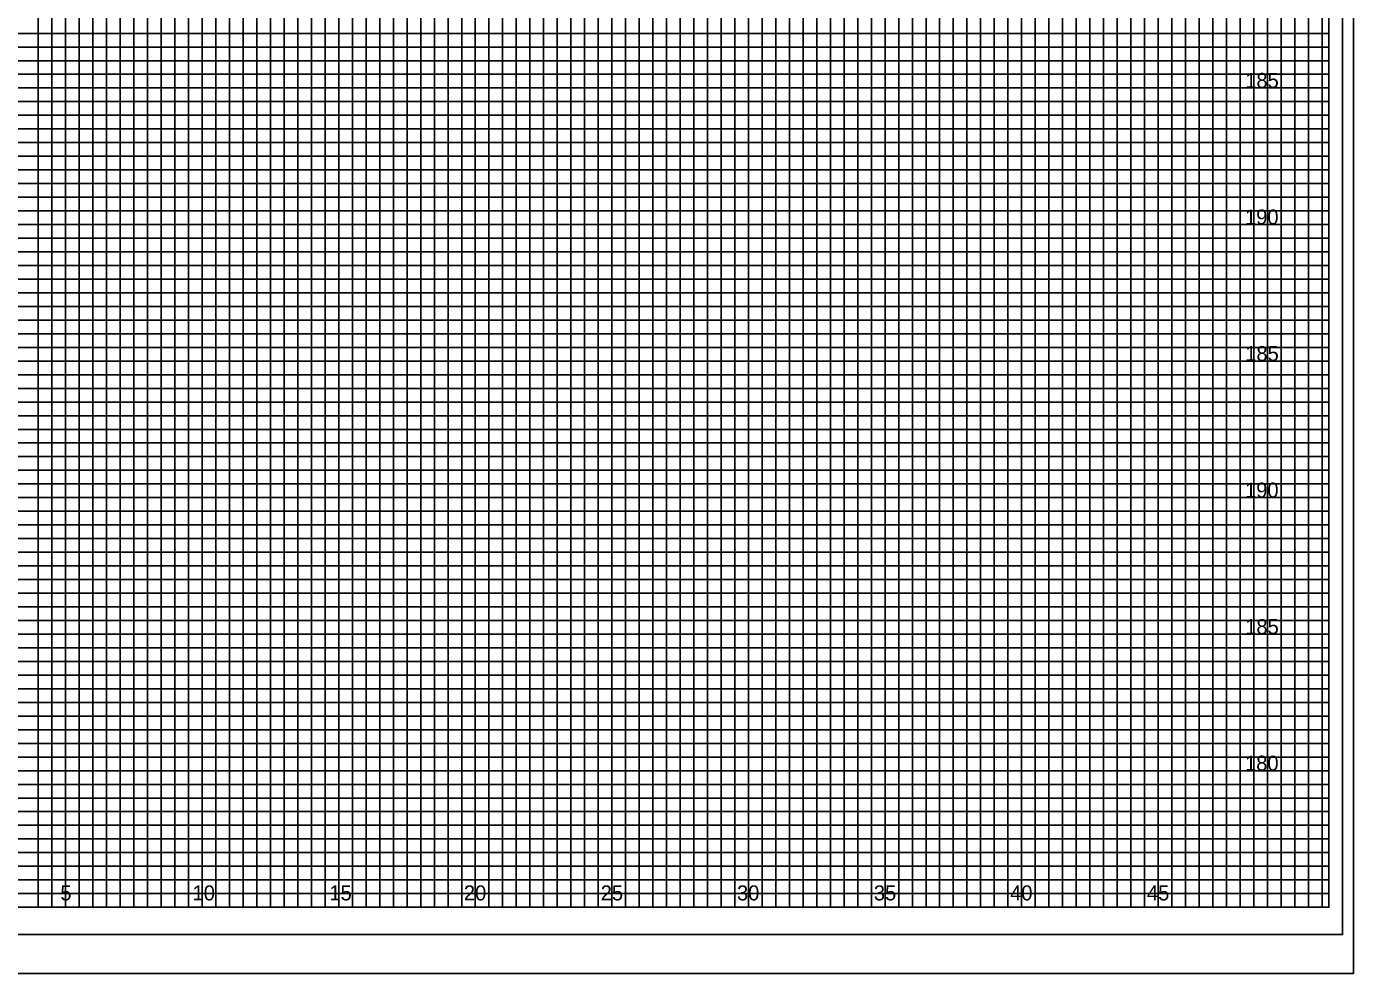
# Model space of a CAD drawing. Extents: x -4 to 103, y -2 to 138.
# Drawn here: x 54.82 to 103.4, y -2.43 to 32.25 of the extents above; entities that cross this region are included whole.
import ezdxf

# ---------------------------------------------------------------- set-up
doc = ezdxf.new("R2010")
doc.units = 0
for name, color, linetype in [('Old_Level_10', 7, 'Continuous'), ('Old_Level_16', 7, 'Continuous'), ('Old_Level_3', 7, 'Continuous'), ('Old_Level_5', 7, 'Continuous'), ('Old_Level_8', 7, 'Continuous'), ('Prop Dimension', 7, 'Continuous'), ('Prop XS SE Text', 7, 'Continuous'), ('Prop XS Subgrade Earthwork', 7, 'Continuous'), ('Prop XSC Text', 7, 'Continuous')]:
    doc.layers.add(name, color=color, linetype=linetype)

msp = doc.modelspace()

# ---------------------------------------------------------------- linework, layer by layer
at = {"layer": 'Old_Level_10'}
for p, q in [((56.25, 0), (56.25, 65)), ((58.75, 0), (58.75, 65)), ((61.25, 0), (61.25, 65)), ((63.75, 0), (63.75, 65)), ((66.25, 0), (66.25, 65)), ((68.75, 0), (68.75, 65)), ((71.25, 0), (71.25, 65)), ((73.75, 0), (73.75, 65)), ((91.25, 0), (91.25, 63.425)), ((93.75, 0), (93.75, 63.425)), ((96.25, 0), (96.25, 63.425)), ((98.75, 0), (98.75, 63.425)), ((101.25, 0), (101.25, 63.425)), ((76.25, 0), (76.25, 62)), ((78.75, 0), (78.75, 62)), ((81.25, 0), (81.25, 62)), ((83.75, 0), (83.75, 62)), ((86.25, 0), (86.25, 62)), ((88.75, 0), (88.75, 62)), ((0, 30), (102.5, 30)), ((0, 27.5), (102.5, 27.5)), ((0, 25), (102.5, 25)), ((0, 22.5), (102.5, 22.5)), ((0, 20), (102.5, 20)), ((0, 17.5), (102.5, 17.5)), ((0, 15), (102.5, 15)), ((0, 12.5), (102.5, 12.5)), ((0, 10), (102.5, 10)), ((0, 7.5), (102.5, 7.5)), ((0, 5), (102.5, 5)), ((0, 2.5), (102.5, 2.5))]:
    msp.add_line(p, q, dxfattribs=at)
at = {"layer": 'Old_Level_3'}
msp.add_line((-3.5, -2.425), (103.4, -2.425), dxfattribs=at)
at = {"layer": 'Old_Level_5'}
msp.add_lwpolyline([(103.4, 67.4), (-3.5, 67.4), (-3.5, -2.425), (103.4, -2.425)], close=True, dxfattribs=at)
at = {"layer": 'Old_Level_8'}
for points in [[(56.25, 0), (56.25, 65)], [(58.75, 65), (58.75, 0), (61.25, 0), (61.25, 65)], [(63.75, 65), (63.75, 0), (66.25, 0), (66.25, 65)], [(68.75, 65), (68.75, 0), (71.25, 0), (71.25, 65)], [(73.75, 65), (73.75, 0), (76.25, 0), (76.25, 62)], [(88.75, 62), (88.75, 0), (91.25, 0), (91.25, 63.425)], [(93.75, 63.425), (93.75, 0), (96.25, 0), (96.25, 63.425)], [(98.75, 63.425), (98.75, 0), (101.25, 0), (101.25, 63.425)], [(78.75, 62), (78.75, 0), (81.25, 0), (81.25, 62)], [(83.75, 62), (83.75, 0), (86.25, 0), (86.25, 62)], [(0, 27.5), (102.5, 27.5), (102.5, 30), (0, 30)], [(0, 22.5), (102.5, 22.5), (102.5, 25), (0, 25)], [(0, 17.5), (102.5, 17.5), (102.5, 20), (0, 20)], [(0, 12.5), (102.5, 12.5), (102.5, 15), (0, 15)], [(0, 7.5), (102.5, 7.5), (102.5, 10), (0, 10)], [(0, 2.5), (102.5, 2.5), (102.5, 5), (0, 5)]]:
    msp.add_lwpolyline(points, dxfattribs=at)
at = {"layer": 'Prop Dimension'}
for points in [[(54.75, 0), (55.25, 0), (55.25, 65)], [(55.75, 65), (55.75, 0), (56.75, 0), (56.75, 65)], [(57.25, 65), (57.25, 0), (57.75, 0), (57.75, 65)], [(58.25, 65), (58.25, 0), (59.25, 0), (59.25, 65)], [(59.75, 65), (59.75, 0), (60.25, 0), (60.25, 65)], [(60.75, 65), (60.75, 0), (61.75, 0), (61.75, 65)], [(62.25, 65), (62.25, 0), (62.75, 0), (62.75, 65)], [(63.25, 65), (63.25, 0), (64.25, 0), (64.25, 65)], [(64.75, 65), (64.75, 0), (65.25, 0), (65.25, 65)], [(65.75, 65), (65.75, 0), (66.75, 0), (66.75, 65)], [(67.25, 65), (67.25, 0), (67.75, 0), (67.75, 65)], [(68.25, 65), (68.25, 0), (69.25, 0), (69.25, 65)], [(69.75, 65), (69.75, 0), (70.25, 0), (70.25, 65)], [(70.75, 65), (70.75, 0), (71.75, 0), (71.75, 65)], [(72.25, 65), (72.25, 0), (72.75, 0), (72.75, 65)], [(73.25, 65), (73.25, 0), (74.25, 0), (74.25, 62)], [(89.75, 62), (89.75, 0), (90.25, 0), (90.25, 63.425)], [(90.75, 63.425), (90.75, 0), (91.75, 0), (91.75, 63.425)], [(92.25, 63.425), (92.25, 0), (92.75, 0), (92.75, 63.425)], [(93.25, 63.425), (93.25, 0), (94.25, 0), (94.25, 63.425)], [(94.75, 63.425), (94.75, 0), (95.25, 0), (95.25, 63.425)], [(95.75, 63.425), (95.75, 0), (96.75, 0), (96.75, 63.425)], [(97.25, 63.425), (97.25, 0), (97.75, 0), (97.75, 63.425)], [(98.25, 63.425), (98.25, 0), (99.25, 0), (99.25, 63.425)], [(99.75, 63.425), (99.75, 0), (100.25, 0), (100.25, 63.425)], [(100.25, 63.425), (100.75, 63.425), (100.75, 0), (101.75, 0), (101.75, 63.425), (102.25, 63.425), (102.25, 0)], [(74.75, 62), (74.75, 0), (75.25, 0), (75.25, 62)], [(75.75, 62), (75.75, 0), (76.75, 0), (76.75, 62)], [(77.25, 62), (77.25, 0), (77.75, 0), (77.75, 62)], [(78.25, 62), (78.25, 0), (79.25, 0), (79.25, 62)], [(79.75, 62), (79.75, 0), (80.25, 0), (80.25, 62)], [(80.75, 62), (80.75, 0), (81.75, 0), (81.75, 62)], [(82.25, 62), (82.25, 0), (82.75, 0), (82.75, 62)], [(83.25, 62), (83.25, 0), (84.25, 0), (84.25, 62)], [(84.75, 62), (84.75, 0), (85.25, 0), (85.25, 62)], [(85.75, 62), (85.75, 0), (86.75, 0), (86.75, 62)], [(87.25, 62), (87.25, 0), (87.75, 0), (87.75, 62)], [(88.25, 62), (88.25, 0), (89.25, 0), (89.25, 62)], [(0, 31.5), (102.5, 31.5), (102.5, 32), (0, 32)], [(0, 30.5), (102.5, 30.5), (102.5, 31), (0, 31)], [(0, 29), (102.5, 29), (102.5, 29.5), (0, 29.5)], [(0, 28), (102.5, 28), (102.5, 28.5), (0, 28.5)], [(0, 26.5), (102.5, 26.5), (102.5, 27), (0, 27)], [(0, 25.5), (102.5, 25.5), (102.5, 26), (0, 26)], [(0, 24), (102.5, 24), (102.5, 24.5), (0, 24.5)], [(0, 23), (102.5, 23), (102.5, 23.5), (0, 23.5)], [(0, 21.5), (102.5, 21.5), (102.5, 22), (0, 22)], [(0, 20.5), (102.5, 20.5), (102.5, 21), (0, 21)], [(0, 19), (102.5, 19), (102.5, 19.5), (0, 19.5)], [(0, 18), (102.5, 18), (102.5, 18.5), (0, 18.5)], [(0, 16.5), (102.5, 16.5), (102.5, 17), (0, 17)], [(0, 15.5), (102.5, 15.5), (102.5, 16), (0, 16)], [(0, 14), (102.5, 14), (102.5, 14.5), (0, 14.5)], [(0, 13), (102.5, 13), (102.5, 13.5), (0, 13.5)], [(0, 11.5), (102.5, 11.5), (102.5, 12), (0, 12)], [(0, 10.5), (102.5, 10.5), (102.5, 11), (0, 11)], [(0, 9), (102.5, 9), (102.5, 9.5), (0, 9.5)], [(0, 8), (102.5, 8), (102.5, 8.5), (0, 8.5)], [(0, 6.5), (102.5, 6.5), (102.5, 7), (0, 7)], [(0, 5.5), (102.5, 5.5), (102.5, 6), (0, 6)], [(0, 4), (102.5, 4), (102.5, 4.5), (0, 4.5)], [(0, 3), (102.5, 3), (102.5, 3.5), (0, 3.5)], [(0, 1.5), (102.5, 1.5), (102.5, 2), (0, 2)], [(0, 0.5), (102.5, 0.5), (102.5, 1), (0, 1)]]:
    msp.add_lwpolyline(points, dxfattribs=at)
at = {"layer": 'Prop XS SE Text'}
msp.add_lwpolyline([(103, 66), (-2.8, 66), (-2.8, -1), (103, -1)], close=True, dxfattribs=at)
at = {"layer": 'Prop XSC Text'}
msp.add_lwpolyline([(102.5, 65), (0, 65), (0, 0), (102.5, 0)], close=True, dxfattribs=at)

# ---------------------------------------------------------------- texts
at = {"layer": 'Old_Level_16'}
for s, p in [('5', (56.057, 0.25)), ('10', (60.897, 0.25)), ('15', (65.906, 0.25)), ('20', (70.831, 0.25)), ('25', (75.84, 0.25)), ('30', (80.831, 0.25)), ('35', (85.84, 0.25)), ('40', (90.831, 0.25)), ('45', (95.84, 0.25))]:
    msp.add_text(s, height=0.55, dxfattribs=at).set_placement(p)
at = {"layer": 'Prop XS Subgrade Earthwork'}
for s, p in [('185', (99.438, 30)), ('190', (99.43, 25)), ('185', (99.438, 20)), ('190', (99.43, 15)), ('185', (99.438, 10)), ('180', (99.43, 5))]:
    msp.add_text(s, height=0.55, dxfattribs=at).set_placement(p)

doc.saveas('drawing.dxf')
